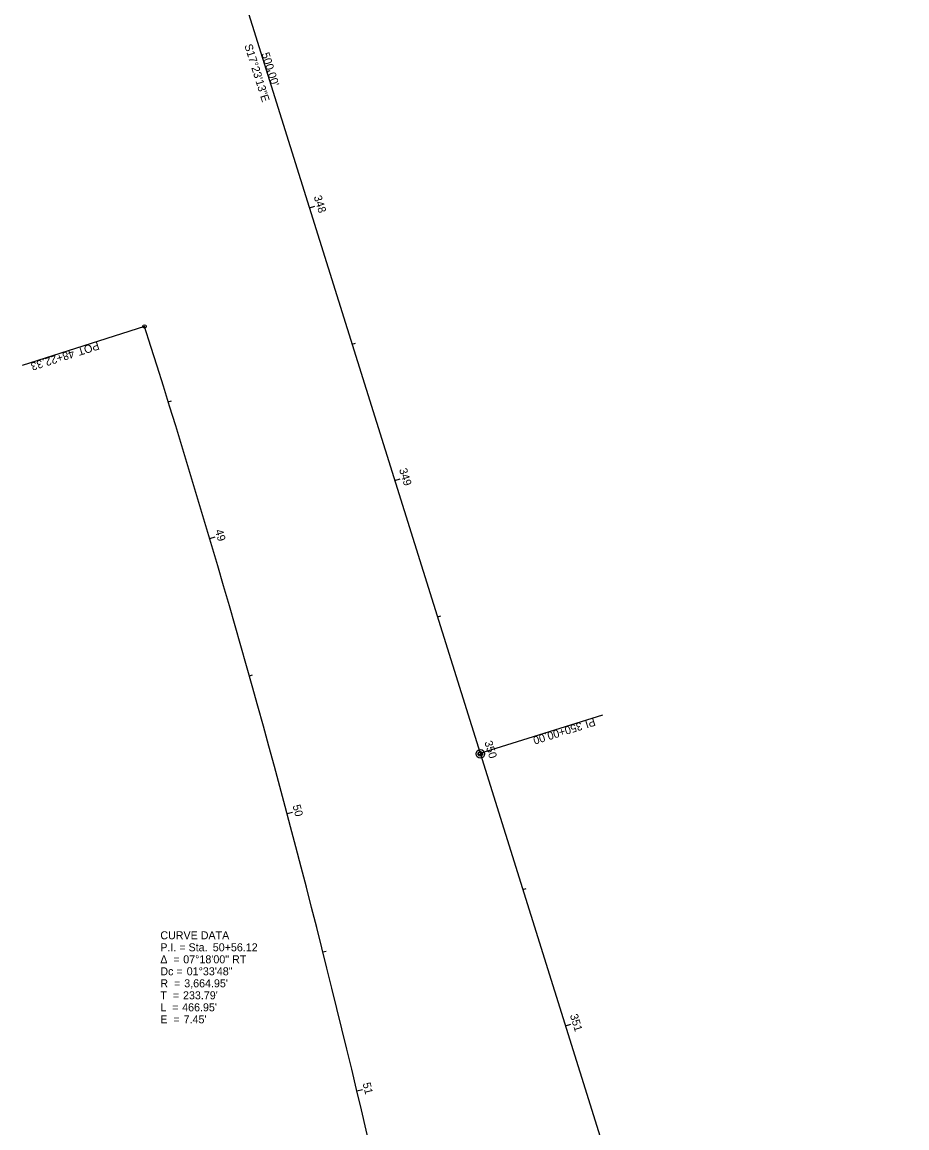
# Model space of a CAD drawing. Extents: x 1918148 to 1920349, y 624677 to 627727.
# Drawn here: x 1918707 to 1919016.8, y 626957 to 627343.9 of the extents above; entities that cross this region are included whole.
import ezdxf

# ---------------------------------------------------------------- set-up
doc = ezdxf.new("R2010")
doc.units = 0
for name, color, linetype in [('_CIVIL_CONSTRUCTION', 7, 'Continuous'), ('RS_Raster1', 7, 'Continuous'), ('RW_X_CL', 7, 'Continuous'), ('RW_X_CL_100_Bearings', 7, 'Continuous'), ('RW_X_CL_100_Cardinal_Points', 7, 'Continuous'), ('RW_X_CL_100_Curve_Data', 7, 'Continuous'), ('SV_X_Mon_Cells_Found', 7, 'Continuous')]:
    doc.layers.add(name, color=color, linetype=linetype)

msp = doc.modelspace()

# ---------------------------------------------------------------- linework, layer by layer
at = {"layer": 'RS_Raster1'}
for p, q in [((1918717.94, 627565.23), (1918867.35, 627088.08)), ((1918867.35, 627088.08), (1919016.77, 626610.92))]:
    msp.add_line(p, q, dxfattribs=at)
msp.add_arc((1915258.46, 626122.9), 3664.95, 10.40444, 17.70444, dxfattribs=at)
at = {"layer": 'RW_X_CL'}
for p, q in [((1918749.83, 627237.44), (1918706.96, 627223.75)), ((1918867.35, 627088.08), (1918910.3, 627101.52))]:
    msp.add_line(p, q, dxfattribs=at)
for centre in [(1918749.83, 627237.44), (1918867.35, 627088.08)]:
    msp.add_circle(centre, 0.6, dxfattribs=at)
at = {"layer": 'RW_X_CL_100_Cardinal_Points'}
for p, q in [((1918792.65, 627326.65), (1918793.79, 627327.01)), ((1918807.59, 627278.94), (1918809.5, 627279.54)), ((1918822.53, 627231.22), (1918823.68, 627231.58)), ((1918758.15, 627211.04), (1918759.29, 627211.4)), ((1918837.47, 627183.51), (1918839.38, 627184.1)), ((1918772.67, 627163.2), (1918774.58, 627163.77)), ((1918852.41, 627135.79), (1918853.56, 627136.15)), ((1918786.53, 627115.16), (1918787.69, 627115.49)), ((1918867.35, 627088.08), (1918869.26, 627088.67)), ((1918799.74, 627066.94), (1918801.67, 627067.45)), ((1918882.3, 627040.36), (1918883.44, 627040.72)), ((1918812.29, 627018.54), (1918813.45, 627018.83)), ((1918897.24, 626992.65), (1918899.15, 626993.24)), ((1918824.18, 626969.97), (1918826.12, 626970.43))]:
    msp.add_line(p, q, dxfattribs=at)
at = {"layer": 'SV_X_Mon_Cells_Found'}
for radius in [1.5, 0.8]:
    msp.add_circle((1918867.41, 627087.89), radius, dxfattribs=at)

# ---------------------------------------------------------------- texts
at = {"layer": '_CIVIL_CONSTRUCTION'}
msp.add_text('S17°23\'13"E', height=2.8, rotation=287.387, dxfattribs=at).set_placement((1918784.76, 627335.79))
at = {"layer": 'RW_X_CL'}
for s, rotation, p in [('POT', 197.7044, (1918733.44, 627232.15)), ('48+22.33', 197.7044, (1918724.74, 627229.38)), ('PI', 197.387, (1918907.17, 627100.49)), ('350+00.00', 197.387, (1918902.6, 627099.06))]:
    msp.add_text(s, height=2.8, rotation=rotation, dxfattribs=at).set_placement(p)
at = {"layer": 'RW_X_CL_100_Bearings'}
for s, p in [('CURVE DATA', (1918755.36, 627022.97)), ('P.I. = Sta. ', (1918755.36, 627018.77)), ('50+56.12', (1918773.73, 627018.77)), ('Δ  = ', (1918755.36, 627014.57)), ('07°18\'00" RT', (1918763.39, 627014.57)), ('Dc = ', (1918755.36, 627010.37)), ('01°33\'48"', (1918764.6, 627010.37)), ('R  = ', (1918755.36, 627006.17)), ("3,664.95'", (1918763.73, 627006.17)), ('T  = ', (1918755.36, 627001.97)), ("233.79'", (1918763.3, 627001.97)), ('L  = ', (1918755.36, 626997.77)), ("466.95'", (1918763.01, 626997.77)), ('E  = ', (1918755.36, 626993.57)), ("7.45'", (1918763.52, 626993.57))]:
    msp.add_text(s, height=2.8, dxfattribs=at).set_placement(p)
at = {"layer": 'RW_X_CL_100_Cardinal_Points'}
for s, rotation, p in [('348', 287.387, (1918809.04, 627282.83)), ('349', 287.387, (1918838.93, 627187.37)), ('49', 286.4902, (1918774.49, 627166)), ('350', 287.387, (1918868.8, 627091.97)), ('50', 284.9268, (1918801.64, 627069.71)), ('351', 287.387, (1918898.74, 626996.38)), ('51', 283.3635, (1918826.19, 626972.53))]:
    msp.add_text(s, height=2.8, rotation=rotation, dxfattribs=at).set_placement(p)
at = {"layer": 'RW_X_CL_100_Curve_Data'}
msp.add_text("500.00'", height=2.8, rotation=287.387, dxfattribs=at).set_placement((1918790.76, 627332.86))

doc.saveas('drawing.dxf')
